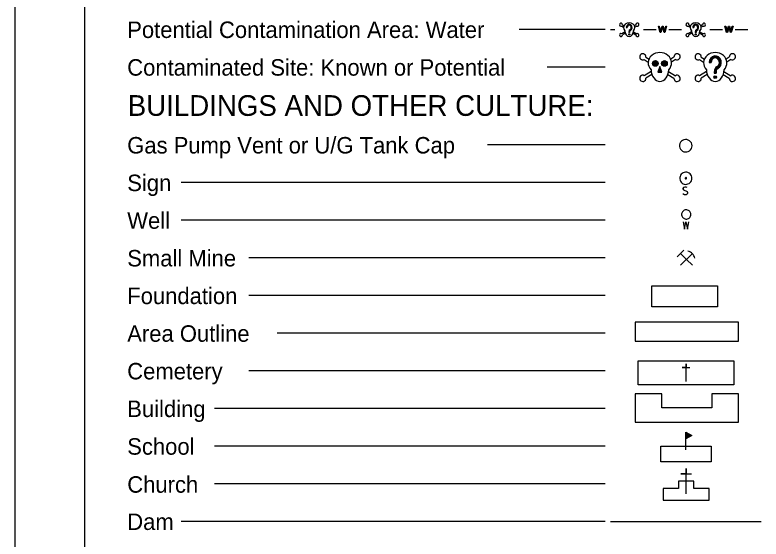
# Model space of a CAD drawing. Extents: x 1552903 to 1553044, y 811448 to 811540.
# Drawn here: x 1552902.56 to 1552935.92, y 811471.45 to 811494.85 of the extents above; entities that cross this region are included whole.
import ezdxf

# ---------------------------------------------------------------- set-up
doc = ezdxf.new("R2010")
doc.units = 0
for name, color, linetype in [('Exist DTM Breakline', 7, 'Continuous'), ('Exist Structure Major Bridge WW', 7, 'Continuous'), ('z - Construction', 7, 'Continuous')]:
    doc.layers.add(name, color=color, linetype=linetype)

msp = doc.modelspace()

# ---------------------------------------------------------------- linework, layer by layer
at = {"layer": 'Exist DTM Breakline'}
for p, q in [((1552929.691, 811494.358), (1552929.775, 811494.305)), ((1552929.724, 811494.412), (1552929.793, 811494.369)), ((1552929.896, 811494.293), (1552929.936, 811494.293)), ((1552930.328, 811494.412), (1552930.259, 811494.369)), ((1552930.361, 811494.358), (1552930.277, 811494.305)), ((1552932.663, 811494.358), (1552932.748, 811494.305)), ((1552932.696, 811494.412), (1552932.765, 811494.369)), ((1552932.868, 811494.293), (1552932.908, 811494.293)), ((1552933.3, 811494.412), (1552933.231, 811494.369)), ((1552933.333, 811494.358), (1552933.249, 811494.305)), ((1552928.953, 811494.204), (1552925.104, 811494.204)), ((1552929.195, 811494.205), (1552929.389, 811494.205)), ((1552929.839, 811494.104), (1552929.691, 811494.011)), ((1552929.853, 811494.039), (1552929.724, 811493.958)), ((1552930.006, 811494.104), (1552930.006, 811494.069)), ((1552930.006, 811494.069), (1552930.046, 811494.069)), ((1552930.012, 811494.104), (1552930.012, 811494.069)), ((1552930.017, 811494.104), (1552930.017, 811494.069)), ((1552930.023, 811494.104), (1552930.023, 811494.069)), ((1552930.026, 811494.205), (1552930.026, 811494.205)), ((1552930.029, 811494.104), (1552930.029, 811494.069)), ((1552930.035, 811494.104), (1552930.035, 811494.069)), ((1552930.04, 811494.104), (1552930.04, 811494.069)), ((1552930.046, 811494.104), (1552930.046, 811494.069)), ((1552930.199, 811494.039), (1552930.328, 811493.958)), ((1552930.213, 811494.104), (1552930.361, 811494.011)), ((1552930.663, 811494.205), (1552931.229, 811494.205)), ((1552931.795, 811494.205), (1552932.361, 811494.205)), ((1552932.811, 811494.104), (1552932.663, 811494.011)), ((1552932.825, 811494.039), (1552932.696, 811493.958)), ((1552932.978, 811494.104), (1552932.978, 811494.069)), ((1552932.978, 811494.069), (1552933.018, 811494.069)), ((1552932.984, 811494.104), (1552932.984, 811494.069)), ((1552932.99, 811494.104), (1552932.99, 811494.069)), ((1552932.995, 811494.104), (1552932.995, 811494.069)), ((1552932.998, 811494.205), (1552932.998, 811494.205)), ((1552933.001, 811494.104), (1552933.001, 811494.069)), ((1552933.007, 811494.104), (1552933.007, 811494.069)), ((1552933.012, 811494.104), (1552933.012, 811494.069)), ((1552933.018, 811494.104), (1552933.018, 811494.069)), ((1552933.171, 811494.039), (1552933.3, 811493.958)), ((1552933.185, 811494.104), (1552933.333, 811494.011)), ((1552933.635, 811494.205), (1552934.201, 811494.205)), ((1552934.767, 811494.205), (1552935.333, 811494.205)), ((1552930.771, 811492.973), (1552930.914, 811492.884)), ((1552932.026, 811492.973), (1552931.883, 811492.884)), ((1552933.245, 811492.973), (1552933.388, 811492.884)), ((1552934.5, 811492.973), (1552934.357, 811492.884)), ((1552930.701, 811492.862), (1552930.877, 811492.751)), ((1552932.096, 811492.862), (1552931.919, 811492.751)), ((1552933.175, 811492.862), (1552933.352, 811492.751)), ((1552933.603, 811492.727), (1552933.686, 811492.727)), ((1552934.57, 811492.862), (1552934.394, 811492.751)), ((1552928.953, 811492.523), (1552926.36, 811492.523)), ((1552931.009, 811492.334), (1552930.701, 811492.141)), ((1552931.398, 811492.501), (1552931.398, 811492.501)), ((1552931.788, 811492.334), (1552932.096, 811492.141)), ((1552933.483, 811492.334), (1552933.175, 811492.141)), ((1552933.831, 811492.333), (1552933.831, 811492.26)), ((1552933.831, 811492.26), (1552933.914, 811492.26)), ((1552933.843, 811492.333), (1552933.843, 811492.26)), ((1552933.855, 811492.333), (1552933.855, 811492.26)), ((1552933.867, 811492.333), (1552933.867, 811492.26)), ((1552933.873, 811492.544), (1552933.873, 811492.544)), ((1552933.879, 811492.333), (1552933.879, 811492.26)), ((1552933.891, 811492.333), (1552933.891, 811492.26)), ((1552933.902, 811492.333), (1552933.902, 811492.26)), ((1552933.914, 811492.333), (1552933.914, 811492.26)), ((1552934.262, 811492.334), (1552934.57, 811492.141)), ((1552931.039, 811492.198), (1552930.771, 811492.03)), ((1552931.758, 811492.198), (1552932.026, 811492.03)), ((1552933.513, 811492.198), (1552933.245, 811492.03)), ((1552934.233, 811492.198), (1552934.5, 811492.03)), ((1552928.953, 811489.047), (1552923.691, 811489.047)), ((1552928.953, 811487.365), (1552910, 811487.365)), ((1552928.953, 811485.684), (1552910, 811485.684)), ((1552928.953, 811484.002), (1552913.027, 811484.002)), ((1552932.326, 811484.2), (1552932.174, 811484.048)), ((1552932.326, 811483.677), (1552932.849, 811484.2)), ((1552932.588, 811483.939), (1552932.558, 811483.968)), ((1552932.588, 811483.939), (1552932.849, 811483.677)), ((1552931.037, 811482.761), (1552933.98, 811482.761)), ((1552931.037, 811481.82), (1552931.037, 811482.761)), ((1552933.98, 811482.761), (1552933.98, 811481.82)), ((1552928.953, 811482.32), (1552913.027, 811482.32)), ((1552933.98, 811481.82), (1552931.037, 811481.82)), ((1552934.911, 811481.127), (1552930.287, 811481.127)), ((1552930.287, 811481.127), (1552930.287, 811480.286)), ((1552934.911, 811480.286), (1552934.911, 811481.127)), ((1552928.953, 811480.639), (1552914.284, 811480.639)), ((1552930.287, 811480.286), (1552934.911, 811480.286)), ((1552930.426, 811479.413), (1552934.702, 811479.413)), ((1552930.426, 811478.337), (1552930.426, 811479.413)), ((1552934.702, 811479.413), (1552934.702, 811478.337)), ((1552928.953, 811478.957), (1552913.027, 811478.957)), ((1552934.702, 811478.337), (1552930.426, 811478.337)), ((1552931.478, 811477.935), (1552930.287, 811477.935)), ((1552930.287, 811477.935), (1552930.287, 811476.674)), ((1552931.478, 811477.304), (1552931.478, 811477.935)), ((1552934.911, 811477.935), (1552933.72, 811477.935)), ((1552933.72, 811477.935), (1552933.72, 811477.304)), ((1552934.911, 811476.674), (1552934.911, 811477.935)), ((1552928.953, 811477.276), (1552911.489, 811477.276)), ((1552933.72, 811477.304), (1552931.478, 811477.304)), ((1552930.287, 811476.674), (1552934.911, 811476.674)), ((1552928.953, 811475.594), (1552911.489, 811475.594)), ((1552931.437, 811475.594), (1552933.684, 811475.594)), ((1552931.437, 811474.896), (1552931.437, 811475.594)), ((1552933.684, 811475.594), (1552933.684, 811474.896)), ((1552933.684, 811474.896), (1552931.437, 811474.896)), ((1552928.953, 811473.913), (1552911.489, 811473.913)), ((1552932.912, 811474.038), (1552932.231, 811474.038)), ((1552932.231, 811474.038), (1552932.231, 811473.698)), ((1552932.912, 811473.698), (1552932.912, 811474.038)), ((1552932.231, 811473.698), (1552931.55, 811473.698)), ((1552931.55, 811473.698), (1552931.55, 811473.186)), ((1552933.593, 811473.698), (1552932.912, 811473.698)), ((1552933.593, 811473.186), (1552933.593, 811473.698)), ((1552931.55, 811473.186), (1552933.593, 811473.186)), ((1552928.953, 811472.231), (1552910, 811472.231)), ((1552929.195, 811472.231), (1552935.921, 811472.231))]:
    msp.add_line(p, q, dxfattribs=at)
for points in [[(1552931.506, 811494.28), (1552931.446, 811494.064), (1552931.408, 811494.064), (1552931.332, 811494.347), (1552931.371, 811494.347), (1552931.414, 811494.161)], [(1552931.439, 811494.156), (1552931.493, 811494.347), (1552931.538, 811494.347), (1552931.578, 811494.204)], [(1552931.614, 811494.165), (1552931.659, 811494.347), (1552931.696, 811494.347), (1552931.619, 811494.064), (1552931.583, 811494.064), (1552931.523, 811494.28)], [(1552934.478, 811494.28), (1552934.418, 811494.064), (1552934.38, 811494.064), (1552934.305, 811494.347), (1552934.343, 811494.347), (1552934.386, 811494.161)], [(1552934.411, 811494.156), (1552934.465, 811494.347), (1552934.51, 811494.347), (1552934.551, 811494.204)], [(1552934.587, 811494.165), (1552934.631, 811494.347), (1552934.669, 811494.347), (1552934.591, 811494.064), (1552934.555, 811494.064), (1552934.495, 811494.28)], [(1552932.84, 811489.011), (1552932.825, 811489.078), (1552932.81, 811489.138), (1552932.773, 811489.19), (1552932.721, 811489.234), (1552932.669, 811489.264), (1552932.609, 811489.287), (1552932.542, 811489.287), (1552932.475, 811489.279), (1552932.415, 811489.249), (1552932.363, 811489.212), (1552932.326, 811489.167), (1552932.296, 811489.108), (1552932.281, 811489.041), (1552932.281, 811488.981), (1552932.296, 811488.914), (1552932.326, 811488.855), (1552932.363, 811488.81), (1552932.415, 811488.773), (1552932.475, 811488.743), (1552932.542, 811488.735), (1552932.609, 811488.735), (1552932.669, 811488.758), (1552932.721, 811488.788), (1552932.773, 811488.832), (1552932.81, 811488.884), (1552932.825, 811488.944), (1552932.84, 811489.011)], [(1552932.832, 811487.56), (1552932.827, 811487.615), (1552932.81, 811487.67), (1552932.783, 811487.719), (1552932.745, 811487.757), (1552932.701, 811487.79), (1552932.652, 811487.817), (1552932.603, 811487.828), (1552932.543, 811487.833), (1552932.488, 811487.823), (1552932.439, 811487.806), (1552932.39, 811487.779), (1552932.351, 811487.741), (1552932.319, 811487.692), (1552932.297, 811487.642), (1552932.286, 811487.588), (1552932.286, 811487.533), (1552932.297, 811487.478), (1552932.319, 811487.429), (1552932.351, 811487.38), (1552932.39, 811487.342), (1552932.439, 811487.315), (1552932.488, 811487.298), (1552932.543, 811487.287), (1552932.603, 811487.293), (1552932.652, 811487.304), (1552932.701, 811487.331), (1552932.745, 811487.364), (1552932.783, 811487.402), (1552932.81, 811487.451), (1552932.827, 811487.506), (1552932.832, 811487.56)], [(1552932.57, 811487.593), (1552932.554, 811487.593), (1552932.537, 811487.582), (1552932.526, 811487.566), (1552932.532, 811487.549), (1552932.543, 811487.533), (1552932.559, 811487.528), (1552932.575, 811487.533), (1552932.586, 811487.544), (1552932.592, 811487.566), (1552932.586, 811487.582), (1552932.57, 811487.593)], [(1552932.623, 811487.14), (1552932.57, 811487.163), (1552932.509, 811487.163), (1552932.454, 811487.14), (1552932.43, 811487.097), (1552932.43, 811487.081), (1552932.456, 811487.042), (1552932.61, 811486.962), (1552932.636, 811486.925), (1552932.634, 811486.893), (1552932.61, 811486.851), (1552932.565, 811486.827), (1552932.501, 811486.827), (1552932.472, 811486.838), (1552932.43, 811486.867)], [(1552932.782, 811485.945), (1552932.775, 811485.981), (1552932.769, 811486.018), (1552932.752, 811486.051), (1552932.729, 811486.081), (1552932.702, 811486.107), (1552932.672, 811486.127), (1552932.636, 811486.14), (1552932.6, 811486.15), (1552932.563, 811486.15), (1552932.527, 811486.147), (1552932.49, 811486.134), (1552932.461, 811486.117), (1552932.431, 811486.094), (1552932.404, 811486.067), (1552932.388, 811486.034), (1552932.375, 811486.001), (1552932.368, 811485.965), (1552932.368, 811485.925), (1552932.375, 811485.889), (1552932.388, 811485.856), (1552932.404, 811485.823), (1552932.431, 811485.796), (1552932.461, 811485.773), (1552932.49, 811485.756), (1552932.527, 811485.743), (1552932.563, 811485.74), (1552932.6, 811485.74), (1552932.636, 811485.75), (1552932.672, 811485.763), (1552932.702, 811485.783), (1552932.729, 811485.809), (1552932.752, 811485.839), (1552932.769, 811485.872), (1552932.775, 811485.909), (1552932.782, 811485.945)], [(1552932.438, 811485.621), (1552932.491, 811485.284), (1552932.56, 811485.621), (1552932.629, 811485.284), (1552932.687, 811485.621)], [(1552932.588, 811483.939), (1552932.326, 811484.2), (1552932.474, 811484.348)], [(1552932.955, 811483.985), (1552932.942, 811484.044), (1552932.921, 811484.099), (1552932.891, 811484.15), (1552932.853, 811484.192), (1552932.811, 811484.234), (1552932.761, 811484.264), (1552932.706, 811484.289), (1552932.651, 811484.302)], [(1552932.565, 811478.482), (1552932.565, 811479.271), (1552932.565, 811479.103), (1552932.398, 811479.103), (1552932.733, 811479.103)], [(1552932.563, 811475.438), (1552932.563, 811476.226), (1552932.827, 811476.071), (1552932.563, 811475.916), (1552932.579, 811475.94), (1552932.579, 811476.204), (1552932.796, 811476.068), (1552932.594, 811475.95), (1552932.597, 811476.179), (1552932.771, 811476.068), (1552932.613, 811475.978), (1552932.613, 811476.151), (1552932.743, 811476.068), (1552932.631, 811476.005), (1552932.631, 811476.123), (1552932.715, 811476.071), (1552932.647, 811476.03), (1552932.647, 811476.095), (1552932.69, 811476.071), (1552932.663, 811476.055), (1552932.659, 811476.074), (1552932.669, 811476.071)], [(1552932.572, 811473.47), (1552932.572, 811474.605), (1552932.572, 811474.364), (1552932.33, 811474.364), (1552932.813, 811474.364)]]:
    msp.add_lwpolyline(points, dxfattribs=at)
for points in [[(1552931.398, 811492.544), (1552931.306, 811492.292), (1552931.491, 811492.292)], [(1552931.398, 811492.501), (1552931.327, 811492.307), (1552931.47, 811492.307)], [(1552931.398, 811492.459), (1552931.348, 811492.322), (1552931.449, 811492.322)], [(1552931.398, 811492.416), (1552931.369, 811492.337), (1552931.427, 811492.337)], [(1552931.398, 811492.373), (1552931.39, 811492.351), (1552931.406, 811492.351)]]:
    msp.add_lwpolyline(points, close=True, dxfattribs=at)
for centre, radius in [((1552930.027, 811493.981), 0.0287), ((1552930.027, 811493.981), 0.0223), ((1552930.027, 811493.981), 0.0158), ((1552930.027, 811493.981), 0.00942), ((1552930.027, 811493.981), 0.00306), ((1552933, 811493.981), 0.0287), ((1552933, 811493.981), 0.0223), ((1552933, 811493.981), 0.0158), ((1552933, 811493.981), 0.00942), ((1552933, 811493.981), 0.00306), ((1552931.196, 811492.687), 0.125), ((1552931.196, 811492.687), 0.11), ((1552931.196, 811492.687), 0.0953), ((1552931.196, 811492.687), 0.0806), ((1552931.196, 811492.687), 0.0659), ((1552931.196, 811492.687), 0.0512), ((1552931.196, 811492.687), 0.0365), ((1552931.196, 811492.687), 0.0218), ((1552931.196, 811492.687), 0.00706), ((1552931.601, 811492.687), 0.125), ((1552931.601, 811492.687), 0.11), ((1552931.601, 811492.687), 0.0953), ((1552931.601, 811492.687), 0.0806), ((1552931.601, 811492.687), 0.0659), ((1552931.601, 811492.687), 0.0512), ((1552931.601, 811492.687), 0.0365), ((1552931.601, 811492.687), 0.0218), ((1552931.601, 811492.687), 0.00706), ((1552933.876, 811492.079), 0.0596), ((1552933.876, 811492.079), 0.0463), ((1552933.876, 811492.079), 0.0328), ((1552933.876, 811492.079), 0.0196), ((1552933.876, 811492.079), 0.00635)]:
    msp.add_circle(centre, radius, dxfattribs=at)
for centre, radius, start, end in [((1552929.657, 811494.417), 0.0671, 355.8976, 299.8062), ((1552930.395, 811494.417), 0.0671, 240.1938, 184.1024), ((1552932.629, 811494.417), 0.0671, 355.8976, 299.8062), ((1552933.367, 811494.417), 0.0671, 240.1938, 184.1024), ((1552929.657, 811493.953), 0.0671, 60.1938, 4.1024), ((1552930.395, 811493.953), 0.0671, 175.8976, 119.8062), ((1552932.629, 811493.953), 0.0671, 60.1938, 4.1024), ((1552933.367, 811493.953), 0.0671, 175.8976, 119.8062), ((1552930.632, 811492.983), 0.139, 355.8976, 299.8062), ((1552932.165, 811492.983), 0.139, 240.1938, 184.1024), ((1552933.106, 811492.983), 0.139, 355.8976, 299.8062), ((1552934.639, 811492.983), 0.139, 240.1938, 184.1024), ((1552930.632, 811492.02), 0.139, 60.1938, 4.1024), ((1552932.165, 811492.02), 0.139, 175.8976, 119.8062), ((1552933.106, 811492.02), 0.139, 60.1938, 4.1024), ((1552934.639, 811492.02), 0.139, 175.8976, 119.8062)]:
    msp.add_arc(centre, radius, start, end, dxfattribs=at)
for centre, major_axis, ratio, start_param, end_param in [((1552930.026, 811494.285), (0.252, 0), 0.885014, 5.564242, 10.143721), ((1552930.026, 811494.293), (0, 0.144), 0.9, 3.567618, 7.853982), ((1552930.026, 811494.293), (0, 0.138), 0.9, 3.567618, 7.853982), ((1552930.026, 811494.293), (0, 0.132), 0.9, 3.567618, 7.853982), ((1552930.026, 811494.293), (0, 0.125), 0.9, 3.567618, 7.853982), ((1552930.026, 811494.293), (0, 0.119), 0.9, 3.567618, 7.853982), ((1552930.026, 811494.293), (0, 0.113), 0.9, 3.567618, 7.853982), ((1552930.026, 811494.293), (0, 0.106), 0.9, 3.567618, 7.853982), ((1552930.026, 811494.293), (0, 0.0998), 0.9, 3.567618, 7.853982), ((1552932.998, 811494.285), (0.252, 0), 0.885014, 5.564242, 10.143721), ((1552932.998, 811494.293), (0, 0.144), 0.9, 3.567618, 7.853982), ((1552932.998, 811494.293), (0, 0.138), 0.9, 3.567618, 7.853982), ((1552932.998, 811494.293), (0, 0.132), 0.9, 3.567618, 7.853982), ((1552932.998, 811494.293), (0, 0.125), 0.9, 3.567618, 7.853982), ((1552932.998, 811494.293), (0, 0.119), 0.9, 3.567618, 7.853982), ((1552932.998, 811494.293), (0, 0.113), 0.9, 3.567618, 7.853982), ((1552932.998, 811494.293), (0, 0.106), 0.9, 3.567618, 7.853982), ((1552932.998, 811494.293), (0, 0.0998), 0.9, 3.567618, 7.853982), ((1552930.026, 811494.141), (0, -0.252), 0.752542, 4.722735, 7.843636), ((1552930.103, 811494.104), (0, 0.108), 0.9, 0.426026, 1.570796), ((1552930.103, 811494.104), (0, 0.102), 0.9, 0.426026, 1.570796), ((1552930.103, 811494.104), (0, 0.0955), 0.9, 0.426026, 1.570796), ((1552930.103, 811494.104), (0, 0.0892), 0.9, 0.426026, 1.570796), ((1552930.103, 811494.104), (0, 0.0828), 0.9, 0.426026, 1.570796), ((1552930.103, 811494.104), (0, 0.0764), 0.9, 0.426026, 1.570796), ((1552930.103, 811494.104), (0, 0.0701), 0.9, 0.426026, 1.570796), ((1552930.103, 811494.104), (0, 0.0637), 0.9, 0.426026, 1.570796), ((1552932.998, 811494.141), (0, -0.252), 0.752542, 4.722735, 7.843636), ((1552933.076, 811494.104), (0, 0.108), 0.9, 0.426026, 1.570796), ((1552933.076, 811494.104), (0, 0.102), 0.9, 0.426026, 1.570796), ((1552933.076, 811494.104), (0, 0.0955), 0.9, 0.426026, 1.570796), ((1552933.076, 811494.104), (0, 0.0892), 0.9, 0.426026, 1.570796), ((1552933.076, 811494.104), (0, 0.0828), 0.9, 0.426026, 1.570796), ((1552933.076, 811494.104), (0, 0.0764), 0.9, 0.426026, 1.570796), ((1552933.076, 811494.104), (0, 0.0701), 0.9, 0.426026, 1.570796), ((1552933.076, 811494.104), (0, 0.0637), 0.9, 0.426026, 1.570796), ((1552931.398, 811492.71), (0.523, 0), 0.885014, 5.564242, 10.143721), ((1552933.873, 811492.71), (0.523, 0), 0.885014, 5.564242, 10.143721), ((1552933.873, 811492.727), (0, 0.3), 0.9, 3.567618, 7.853982), ((1552933.873, 811492.727), (0, 0.287), 0.9, 3.567618, 7.853982), ((1552933.873, 811492.727), (0, 0.274), 0.9, 3.567618, 7.853982), ((1552933.873, 811492.727), (0, 0.26), 0.9, 3.567618, 7.853982), ((1552933.873, 811492.727), (0, 0.247), 0.9, 3.567618, 7.853982), ((1552933.873, 811492.727), (0, 0.234), 0.9, 3.567618, 7.853982), ((1552933.873, 811492.727), (0, 0.221), 0.9, 3.567618, 7.853982), ((1552933.873, 811492.727), (0, 0.207), 0.9, 3.567618, 7.853982), ((1552931.398, 811492.41), (0, -0.523), 0.752542, 4.722735, 7.843636), ((1552933.873, 811492.41), (0, -0.523), 0.752542, 4.722735, 7.843636), ((1552934.034, 811492.333), (0, 0.225), 0.9, 0.426026, 1.570796), ((1552934.034, 811492.333), (0, 0.212), 0.9, 0.426026, 1.570796), ((1552934.034, 811492.333), (0, 0.199), 0.9, 0.426026, 1.570796), ((1552934.034, 811492.333), (0, 0.185), 0.9, 0.426026, 1.570796), ((1552934.034, 811492.333), (0, 0.172), 0.9, 0.426026, 1.570796), ((1552934.034, 811492.333), (0, 0.159), 0.9, 0.426026, 1.570796), ((1552934.034, 811492.333), (0, 0.146), 0.9, 0.426026, 1.570796), ((1552934.034, 811492.333), (0, 0.132), 0.9, 0.426026, 1.570796)]:
    msp.add_ellipse(centre, major_axis=major_axis, ratio=ratio, start_param=start_param, end_param=end_param, dxfattribs=at)
for points in [[(1552931.514, 811494.313), (1552931.51, 811494.293), (1552931.506, 811494.28)], [(1552931.523, 811494.28), (1552931.516, 811494.307), (1552931.514, 811494.313)], [(1552934.486, 811494.313), (1552934.482, 811494.293), (1552934.478, 811494.28)], [(1552934.495, 811494.28), (1552934.488, 811494.307), (1552934.486, 811494.313)], [(1552931.414, 811494.161), (1552931.421, 811494.132), (1552931.426, 811494.104)], [(1552931.426, 811494.104), (1552931.437, 811494.149), (1552931.439, 811494.156)], [(1552931.578, 811494.204), (1552931.593, 811494.15), (1552931.6, 811494.104)], [(1552931.6, 811494.104), (1552931.606, 811494.13), (1552931.614, 811494.165)], [(1552934.386, 811494.161), (1552934.393, 811494.132), (1552934.398, 811494.104)], [(1552934.398, 811494.104), (1552934.409, 811494.149), (1552934.411, 811494.156)], [(1552934.551, 811494.204), (1552934.566, 811494.15), (1552934.572, 811494.104)], [(1552934.572, 811494.104), (1552934.578, 811494.13), (1552934.587, 811494.165)]]:
    msp.add_open_spline(points, degree=2, dxfattribs=at)
at = {"layer": 'Exist Structure Major Bridge WW'}
msp.add_line((1552905.688, 811451.545), (1552905.688, 811536.962), dxfattribs=at)
at = {"layer": 'z - Construction'}
msp.add_line((1552902.563, 811540.087), (1552902.563, 811448.42), dxfattribs=at)

# ---------------------------------------------------------------- texts
at = {"layer": 'Exist DTM Breakline'}
for s, height, p in [('Potential Contamination Area: Water', 0.73569, (1552907.584, 811493.824)), ('Contaminated Site: Known or Potential', 0.73569, (1552907.584, 811492.142)), ('BUILDINGS AND OTHER CULTURE:', 0.92486, (1552907.607, 811490.346)), ('Gas Pump Vent or U/G Tank Cap', 0.73569, (1552907.584, 811488.666)), ('Sign', 0.7357, (1552907.585, 811486.986)), ('Well', 0.7357, (1552907.585, 811485.304)), ('Small Mine', 0.7357, (1552907.585, 811483.622)), ('Foundation', 0.7357, (1552907.585, 811481.94)), ('Area Outline', 0.73569, (1552907.585, 811480.258)), ('Cemetery', 0.7357, (1552907.584, 811478.578)), ('Building', 0.7357, (1552907.585, 811476.896)), ('School', 0.7357, (1552907.584, 811475.215)), ('Church', 0.7357, (1552907.586, 811473.517)), ('Dam', 0.7357, (1552907.585, 811471.852))]:
    msp.add_text(s, height=height, dxfattribs=at).set_placement(p)

doc.saveas('drawing.dxf')
